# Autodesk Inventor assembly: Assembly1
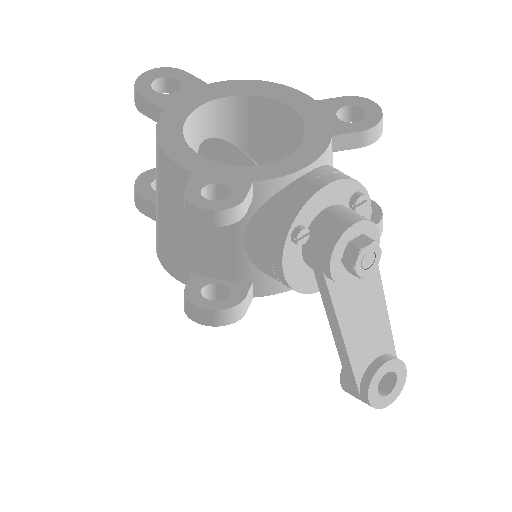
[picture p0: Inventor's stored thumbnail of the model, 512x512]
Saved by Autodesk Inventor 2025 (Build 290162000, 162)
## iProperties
Created: 2019-03
Part Number: Assembly1
Document SubType Name: Assembly
Designer: LENOVO-CADCIM
Author: LENOVO-CADCIM
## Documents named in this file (10)
- D:\CAD\Inventor\Autodesk Inventor 2025\Resources\2025\c09_Inv_2025_tut\c09_tut01_inv\Butterfly Valve\Butterfly Valve assembly.iam
- D:\CAD\Inventor\Autodesk Inventor 2025\Resources\2025\c09_Inv_2025_tut\c09_tut01_inv\Butterfly Valve\Body.ipt
- D:\CAD\Inventor\Autodesk Inventor 2025\Resources\2025\c09_Inv_2025_tut\c09_tut01_inv\Butterfly Valve\Shaft.ipt
- D:\CAD\Inventor\Autodesk Inventor 2025\Resources\2025\c09_Inv_2025_tut\c09_tut01_inv\Butterfly Valve\Retainer.ipt
- D:\CAD\Inventor\Autodesk Inventor 2025\Resources\2025\c09_Inv_2025_tut\c09_tut01_inv\Butterfly Valve\Arm1.ipt
- D:\CAD\Inventor\Autodesk Inventor 2025\Resources\2025\c09_Inv_2025_tut\c09_tut01_inv\Butterfly Valve\Plate.ipt
- D:\CAD\Inventor\Autodesk Inventor 2025\Resources\2025\c09_Inv_2025_tut\c09_tut01_inv\Butterfly Valve\scew1.ipt
- D:\CAD\Inventor\Autodesk Inventor 2025\Resources\2025\c09_Inv_2025_tut\c09_tut01_inv\Butterfly Valve\Screw.ipt
- D:\CAD\Inventor\Autodesk Inventor 2025\Resources\2025\c09_Inv_2025_tut\c09_tut01_inv\Butterfly Valve\Parallel key.ipt
- D:\CAD\Inventor\Autodesk Inventor 2025\Resources\2025\c09_Inv_2025_tut\c09_tut01_inv\Butterfly Valve\Nut.ipt
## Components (12 placed, 9 different names)
1. Body:1 — Insert:1, Insert:2, Mate:1, Angle:4, Angle:5
2. Shaft:1 — Insert:1, Insert:3, Insert:4, Mate:3, Insert:11, Angle:5
3. Retainer:1 — Insert:2, Mate:1, Insert:7, Insert:8, Insert:9, Insert:10
4. Arm1:1 — Insert:10, Mate:2, Flush:1
5. Plate:1 — Insert:3, Insert:4, Insert:5, Insert:6
6. scew1:1 — Insert:5
7. scew1:2 — Insert:6
8. Screw:1 — Insert:7
9. Screw:2 — Insert:8
10. Screw:3 — Insert:9
11. Parallel key:1 — Mate:2, Mate:3, Flush:1
12. Nut:1 — Insert:11, Angle:4
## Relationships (17: Insert 11, Mate 3, Angle 2, Flush 1)
- Insert:1: Body:1 ↔ Shaft:1
- Insert:2: Body:1 ↔ Retainer:1
- Mate:1: Body:1 ↔ Retainer:1
- Insert:3: Shaft:1 ↔ Plate:1
- Insert:4: Shaft:1 ↔ Plate:1
- Insert:5: Plate:1 ↔ scew1:1
- Insert:6: Plate:1 ↔ scew1:2
- Insert:7: Retainer:1 ↔ Screw:1
- Insert:8: Retainer:1 ↔ Screw:2
- Insert:9: Retainer:1 ↔ Screw:3
- Insert:10: Retainer:1 ↔ Arm1:1
- Mate:2: Arm1:1 ↔ Parallel key:1
- Mate:3: Shaft:1 ↔ Parallel key:1
- Flush:1: Arm1:1 ↔ Parallel key:1
- Insert:11: Shaft:1 ↔ Nut:1
- Angle:4: Body:1 ↔ Nut:1
- Angle:5: Body:1 ↔ Shaft:1
